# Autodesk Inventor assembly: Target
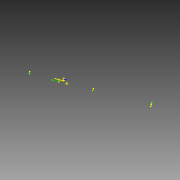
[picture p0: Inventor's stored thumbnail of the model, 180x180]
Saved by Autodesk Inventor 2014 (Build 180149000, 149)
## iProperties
Created: 2009-05
Part Number: Target
Document SubType Name: Assembly
Designer: garding
Author: garding
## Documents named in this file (2)
- C:\Users\iTools\Desktop\tutorial files\iCopy\Target.iam
- C:\Users\iTools\Desktop\tutorial files\iCopy\Path.ipt
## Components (1 placed, 1 different names)
1. Path:1 — Mate:3, Mate:4
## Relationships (2: Mate 2)
- Mate:3: Path:1
- Mate:4: Path:1
